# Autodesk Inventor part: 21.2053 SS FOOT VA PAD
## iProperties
Created: 2011-11
Part Number: 21.2053 SS FOOT VA PAD
Document SubType Name: Modeling
Designer: Administrator
Density: 0.93 g/cm^3
Material: Rubber
Mass: 6.01108 g
Surface Area: 29.7732 cm^2
Volume: 6.46352 cm^3
Author: Administrator
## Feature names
1. Base1
